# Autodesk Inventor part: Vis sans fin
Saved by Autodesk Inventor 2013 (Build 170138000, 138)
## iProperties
Created: 2011-07
Part Number: Vis sans fin
Material: Acier doux
Document SubType Name: Modeling
Designer: Laur
Density: 7.86 g/cm^3
CustomPartVersion: 1
Author: Laur
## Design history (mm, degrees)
node "Solide1"
node "Corps solides"
node "Corps surfaciques"
extrude "Corps de base" new body stored distance "d6" = 8 (= da_b); taper "d7" = 0 deg
chamfer "Chamfer1" distance "d8" = 0.40037 (= fd_cham1); stored, may be unused: second distance "d9" = 1.1 (= 0.5 x fd_cham2), angle "d47" = 45 deg
chamfer "Chamfer2" distance "d10" = 0.40037 (= fd_cham1); stored, may be unused: second distance "d11" = 1.1 (= 0.5 x fd_cham2), angle "d48" = 45 deg
sketch "Esquisse de la dent"
  geometry: L1 (0, 21.74)-(0, 10.96) reference; L2 (-6.115, 2.921)-(-5.705, 1.792); L3 (-5.352, 1.792)-(-4.941, 2.921); L4 (-50.535, 0)-(-37.455, 0) reference; L5 (-6.115, 2.921)-(-5.528, 2.921); L6 (-5.528, 2.921)-(-4.941, 2.921); L7 (-5.705, 1.792)-(-5.528, 1.792); L8 (-5.528, 1.792)-(-5.352, 1.792); L9 (-5.528, 2.392)-(-5.133, 2.392); L10 (-5.528, 2.921)-(-5.528, 1.792)
  constraints: 16 end point, 3 equal length, 3 parallel, 2 collinear, 2 point on line
  dimensions: "d24" = 110 deg angle of L7 L2 (computed from da_alfat); "d25" = 5.52807 distance from line of L1 L5.end (= fd_dist); "d26" = 0.39486 distance of L9.start L9.end (= 0.25 x da_px); "d27" = 1.79169 distance between parallel lines of L4 L7 (= 0.5 x da_df); "d28" = 2.39169 distance between parallel lines of L4 L9 (= 0.5 x da_d); "d29" = 2.92061 distance between parallel lines of L4 L5 (= 0.505 x da_da)
feature "Dent" pitch "d30" = 1.57945 (computed from da_px, da_z); turns "d32" = 8 (= fd_n); dims "d31" = 10, "d33" = 0, angle "d34" = 90 deg, angle "d35" = 90 deg, "d36" = 0, "d37" = 0, "d70" = 10, "da_rightdir" = 10 [user parameter]
pattern_circular "Motif de la dent" dims angle "d46" = 360 deg
feature "Dent gauche" pitch "d62" = 1.57945 (computed from da_px, da_z); turns "d64" = 8 (= fd_n); dims "d63" = 10, "d65" = 0, angle "d66" = 90 deg, angle "d67" = 90 deg, "d68" = 0, "d69" = 0, "d76" = 10, "da_rightdir" = 10 [user parameter]
pattern_circular "Motif de dent gauche" dims angle "d73" = 360 deg
node "Esquisse du corps de base" dims "d5" = 5.78339 (= da_da)
sketch "Sketch5"
  geometry: C1 r 2.892 at (0, 0) reference; C2 r 2.392 at (0, 0)
  constraints: 1 centre point, 1 coincident
  dimensions: "d59" = 4.78339 diameter of C2 (= da_d)
body "Srf1"
extrude_surface "ExtrusionSrf1" dims "d60" = 10, "d61" = 0
other parameters: "da_aw" = 9.93301 [user parameter; used in 2 equation terms], "da_b" = 8 [user parameter; used in 3 equation terms], "da_df" = 3.58339 [user parameter; used in 2 equation terms], "da_da" = 5.78339 [user parameter; used in 3 equation terms], "fd_cham2" = 2.2 (= da_da - da_df) [user parameter; used in 3 equation terms], "fd_cham1" = 0.40037 (= 0.181985 x fd_cham2) [user parameter; used in 2 equation terms], "da_d" = 4.78339 [user parameter; used in 2 equation terms], "da_px" = 1.57945 [user parameter; used in 5 equation terms], "fd_dist" = 5.52807 (computed from da_b, da_px) [user parameter; used in 1 equation term], "fd_n" = 8 (computed from da_b, da_px) [user parameter; used in 2 equation terms], "da_alfat" = 20 deg [user parameter; used in 1 equation term], "d12" = 110 deg (derived), "d14" = 3.1425 (derived), "d49" = 9.93301 (= da_aw), "d50" = 0, "d54" = 0, "d56" = 0, "d77" = 0, "d79" = 9.93301 (= da_aw), "d80" = 0
